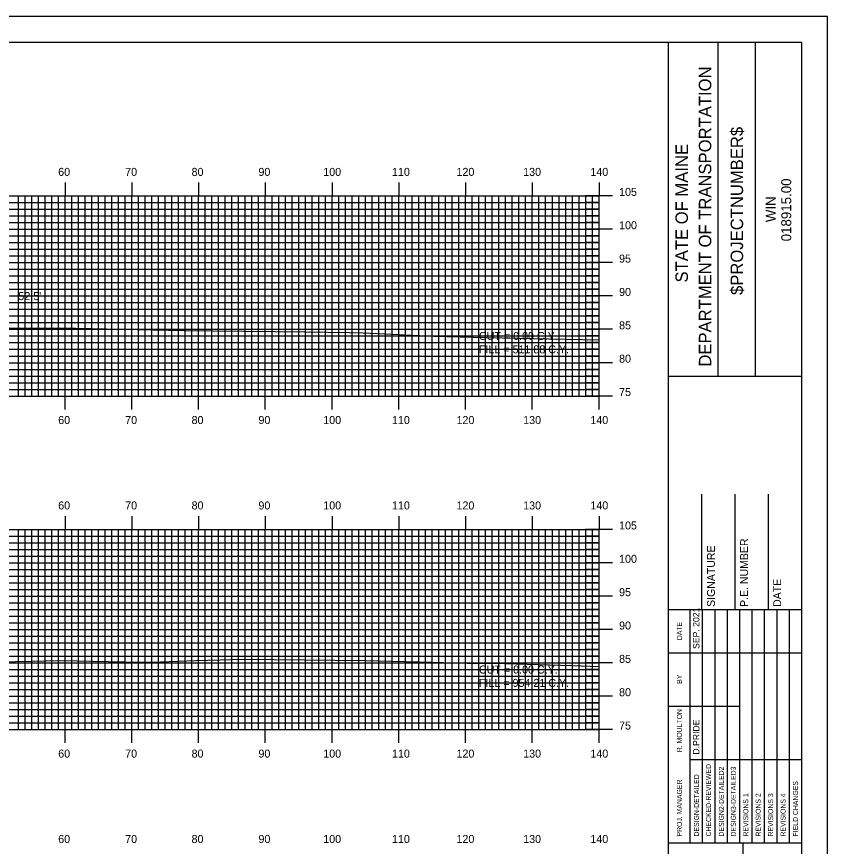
# Model space of a CAD drawing. Extents: x 2059 to 2403, y -1658 to -1438.
# Drawn here: x 2277.9 to 2399.4, y -1562.1 to -1437.7 of the extents above; entities that cross this region are included whole.
import ezdxf

# ---------------------------------------------------------------- set-up
doc = ezdxf.new("R2010")
doc.units = 0
for name, color, linetype in [('BORDER', 7, 'Continuous'), ('D_Text_Standard', 7, 'Continuous'), ('H_V ANNOTATION', 7, 'Continuous'), ('MAJOR', 7, 'Continuous'), ('MINOR', 7, 'Continuous'), ('PLOT BOUNDARY', 7, 'Continuous'), ('S_Roadway_Centerline', 7, 'Continuous')]:
    doc.layers.add(name, color=color, linetype=linetype)

msp = doc.modelspace()

# ---------------------------------------------------------------- linework, layer by layer
at = {"layer": 'BORDER'}
for p, q in [((2375.59, -1651.6), (2375.59, -1441.6)), ((2383.04, -1491.61), (2383.04, -1441.61)), ((2388.63, -1491.61), (2388.63, -1441.61)), ((2375.59, -1491.62), (2395.59, -1491.62)), ((2380.59, -1526.6), (2380.59, -1509.3)), ((2385.59, -1526.6), (2385.59, -1509.3)), ((2390.59, -1526.6), (2390.59, -1509.3)), ((2375.59, -1526.6), (2395.59, -1526.6)), ((2375.59, -1561.6), (2395.59, -1561.6)), ((2386.77, -1631.6), (2386.77, -1561.6))]:
    msp.add_line(p, q, dxfattribs=at)
msp.add_lwpolyline([(2075.59, -1651.6), (2395.59, -1651.6), (2395.59, -1441.6), (2075.59, -1441.6)], close=True, dxfattribs=at)
for points in [[(2378.82, -1533.1), (2378.82, -1526.6)], [(2380.68, -1561.59), (2380.68, -1526.6)], [(2382.54, -1526.6), (2382.54, -1561.59)], [(2384.41, -1561.59), (2384.41, -1526.6)], [(2386.27, -1561.59), (2386.27, -1526.6)], [(2388.14, -1561.59), (2388.14, -1526.6)], [(2390, -1561.59), (2390, -1526.6)], [(2391.86, -1561.59), (2391.86, -1526.6)], [(2393.73, -1561.59), (2393.73, -1526.6)], [(2378.82, -1561.59), (2378.82, -1528.01)], [(2375.59, -1533.1), (2395.59, -1533.1)], [(2375.59, -1541.1), (2378.82, -1541.1)], [(2378.82, -1541.1), (2386.27, -1541.1)], [(2378.82, -1549.1), (2395.59, -1549.1)]]:
    msp.add_lwpolyline(points, dxfattribs=at)
at = {"layer": 'MAJOR'}
for p, q in [((2285.19, -1462.6), (2285.19, -1464.6)), ((2295.19, -1462.6), (2295.19, -1464.6)), ((2305.19, -1462.6), (2305.19, -1464.6)), ((2315.19, -1462.6), (2315.19, -1464.6)), ((2325.19, -1462.6), (2325.19, -1464.6)), ((2335.19, -1462.6), (2335.19, -1464.6)), ((2345.19, -1462.6), (2345.19, -1464.6)), ((2355.19, -1462.6), (2355.19, -1464.6)), ((2365.19, -1462.6), (2365.19, -1464.6)), ((2085.19, -1464.6), (2365.19, -1464.6)), ((2085.19, -1464.6), (2365.19, -1464.6)), ((2285.19, -1494.6), (2285.19, -1464.6)), ((2295.19, -1494.6), (2295.19, -1464.6)), ((2305.19, -1494.6), (2305.19, -1464.6)), ((2315.19, -1494.6), (2315.19, -1464.6)), ((2325.19, -1494.6), (2325.19, -1464.6)), ((2335.19, -1494.6), (2335.19, -1464.6)), ((2345.19, -1494.6), (2345.19, -1464.6)), ((2355.19, -1494.6), (2355.19, -1464.6)), ((2367.19, -1464.6), (2363.18, -1464.6)), ((2365.19, -1494.6), (2365.19, -1464.6)), ((2365.19, -1494.6), (2365.19, -1464.6)), ((2085.19, -1469.6), (2365.19, -1469.6)), ((2367.19, -1469.6), (2363.18, -1469.6)), ((2085.19, -1474.6), (2365.19, -1474.6)), ((2367.19, -1474.6), (2363.18, -1474.6)), ((2085.19, -1479.6), (2365.19, -1479.6)), ((2367.19, -1479.6), (2363.18, -1479.6)), ((2085.19, -1484.6), (2365.19, -1484.6)), ((2367.19, -1484.6), (2363.18, -1484.6)), ((2085.19, -1489.6), (2365.19, -1489.6)), ((2367.19, -1489.6), (2363.18, -1489.6)), ((2085.19, -1494.6), (2365.19, -1494.6)), ((2085.19, -1494.6), (2365.19, -1494.6)), ((2285.19, -1496.61), (2285.19, -1494.6)), ((2295.19, -1496.61), (2295.19, -1494.6)), ((2305.19, -1496.61), (2305.19, -1494.6)), ((2315.19, -1496.61), (2315.19, -1494.6)), ((2325.19, -1496.61), (2325.19, -1494.6)), ((2335.19, -1496.61), (2335.19, -1494.6)), ((2345.19, -1496.61), (2345.19, -1494.6)), ((2355.19, -1496.61), (2355.19, -1494.6)), ((2367.19, -1494.6), (2363.18, -1494.6)), ((2365.19, -1496.61), (2365.19, -1494.6)), ((2285.19, -1512.6), (2285.19, -1514.6)), ((2295.19, -1512.6), (2295.19, -1514.6)), ((2305.19, -1512.6), (2305.19, -1514.6)), ((2315.19, -1512.6), (2315.19, -1514.6)), ((2325.19, -1512.6), (2325.19, -1514.6)), ((2335.19, -1512.6), (2335.19, -1514.6)), ((2345.19, -1512.6), (2345.19, -1514.6)), ((2355.19, -1512.6), (2355.19, -1514.6)), ((2365.19, -1512.6), (2365.19, -1514.6)), ((2085.19, -1514.6), (2365.19, -1514.6)), ((2085.19, -1514.6), (2365.19, -1514.6)), ((2285.19, -1544.6), (2285.19, -1514.6)), ((2295.19, -1544.6), (2295.19, -1514.6)), ((2305.19, -1544.6), (2305.19, -1514.6)), ((2315.19, -1544.6), (2315.19, -1514.6)), ((2325.19, -1544.6), (2325.19, -1514.6)), ((2335.19, -1544.6), (2335.19, -1514.6)), ((2345.19, -1544.6), (2345.19, -1514.6)), ((2355.19, -1544.6), (2355.19, -1514.6)), ((2367.19, -1514.6), (2363.18, -1514.6)), ((2365.19, -1544.6), (2365.19, -1514.6)), ((2365.19, -1544.6), (2365.19, -1514.6)), ((2085.19, -1519.6), (2365.19, -1519.6)), ((2367.19, -1519.6), (2363.18, -1519.6)), ((2085.19, -1524.6), (2365.19, -1524.6)), ((2367.19, -1524.6), (2363.18, -1524.6)), ((2085.19, -1529.6), (2365.19, -1529.6)), ((2367.19, -1529.6), (2363.18, -1529.6)), ((2085.19, -1534.6), (2365.19, -1534.6)), ((2367.19, -1534.6), (2363.18, -1534.6)), ((2085.19, -1539.6), (2365.19, -1539.6)), ((2367.19, -1539.6), (2363.18, -1539.6)), ((2085.19, -1544.6), (2365.19, -1544.6)), ((2085.19, -1544.6), (2365.19, -1544.6)), ((2285.19, -1546.61), (2285.19, -1544.6)), ((2295.19, -1546.61), (2295.19, -1544.6)), ((2305.19, -1546.61), (2305.19, -1544.6)), ((2315.19, -1546.61), (2315.19, -1544.6)), ((2325.19, -1546.61), (2325.19, -1544.6)), ((2335.19, -1546.61), (2335.19, -1544.6)), ((2345.19, -1546.61), (2345.19, -1544.6)), ((2355.19, -1546.61), (2355.19, -1544.6)), ((2367.19, -1544.6), (2363.18, -1544.6)), ((2365.19, -1546.61), (2365.19, -1544.6))]:
    msp.add_line(p, q, dxfattribs=at)
at = {"layer": 'MINOR'}
for p, q in [((2278.19, -1494.6), (2278.19, -1464.6)), ((2279.19, -1494.6), (2279.19, -1464.6)), ((2280.19, -1494.6), (2280.19, -1464.6)), ((2281.19, -1494.6), (2281.19, -1464.6)), ((2282.19, -1494.6), (2282.19, -1464.6)), ((2283.19, -1494.6), (2283.19, -1464.6)), ((2284.19, -1494.6), (2284.19, -1464.6)), ((2286.19, -1494.6), (2286.19, -1464.6)), ((2287.19, -1494.6), (2287.19, -1464.6)), ((2288.19, -1494.6), (2288.19, -1464.6)), ((2289.19, -1494.6), (2289.19, -1464.6)), ((2290.19, -1494.6), (2290.19, -1464.6)), ((2291.19, -1494.6), (2291.19, -1464.6)), ((2292.19, -1494.6), (2292.19, -1464.6)), ((2293.19, -1494.6), (2293.19, -1464.6)), ((2294.19, -1494.6), (2294.19, -1464.6)), ((2296.19, -1494.6), (2296.19, -1464.6)), ((2297.19, -1494.6), (2297.19, -1464.6)), ((2298.19, -1494.6), (2298.19, -1464.6)), ((2299.19, -1494.6), (2299.19, -1464.6)), ((2300.19, -1494.6), (2300.19, -1464.6)), ((2301.19, -1494.6), (2301.19, -1464.6)), ((2302.19, -1494.6), (2302.19, -1464.6)), ((2303.19, -1494.6), (2303.19, -1464.6)), ((2304.19, -1494.6), (2304.19, -1464.6)), ((2306.19, -1494.6), (2306.19, -1464.6)), ((2307.19, -1494.6), (2307.19, -1464.6)), ((2308.19, -1494.6), (2308.19, -1464.6)), ((2309.19, -1494.6), (2309.19, -1464.6)), ((2310.19, -1494.6), (2310.19, -1464.6)), ((2311.19, -1494.6), (2311.19, -1464.6)), ((2312.19, -1494.6), (2312.19, -1464.6)), ((2313.19, -1494.6), (2313.19, -1464.6)), ((2314.19, -1494.6), (2314.19, -1464.6)), ((2316.19, -1494.6), (2316.19, -1464.6)), ((2317.19, -1494.6), (2317.19, -1464.6)), ((2318.19, -1494.6), (2318.19, -1464.6)), ((2319.19, -1494.6), (2319.19, -1464.6)), ((2320.19, -1494.6), (2320.19, -1464.6)), ((2321.19, -1494.6), (2321.19, -1464.6)), ((2322.19, -1494.6), (2322.19, -1464.6)), ((2323.19, -1494.6), (2323.19, -1464.6)), ((2324.19, -1494.6), (2324.19, -1464.6)), ((2326.19, -1494.6), (2326.19, -1464.6)), ((2327.19, -1494.6), (2327.19, -1464.6)), ((2328.19, -1494.6), (2328.19, -1464.6)), ((2329.19, -1494.6), (2329.19, -1464.6)), ((2330.19, -1494.6), (2330.19, -1464.6)), ((2331.19, -1494.6), (2331.19, -1464.6)), ((2332.19, -1494.6), (2332.19, -1464.6)), ((2333.19, -1494.6), (2333.19, -1464.6)), ((2334.19, -1494.6), (2334.19, -1464.6)), ((2336.19, -1494.6), (2336.19, -1464.6)), ((2337.19, -1494.6), (2337.19, -1464.6)), ((2338.19, -1494.6), (2338.19, -1464.6)), ((2339.19, -1494.6), (2339.19, -1464.6)), ((2340.19, -1494.6), (2340.19, -1464.6)), ((2341.19, -1494.6), (2341.19, -1464.6)), ((2342.19, -1494.6), (2342.19, -1464.6)), ((2343.19, -1494.6), (2343.19, -1464.6)), ((2344.19, -1494.6), (2344.19, -1464.6)), ((2346.19, -1494.6), (2346.19, -1464.6)), ((2347.19, -1494.6), (2347.19, -1464.6)), ((2348.19, -1494.6), (2348.19, -1464.6)), ((2349.19, -1494.6), (2349.19, -1464.6)), ((2350.19, -1494.6), (2350.19, -1464.6)), ((2351.19, -1494.6), (2351.19, -1464.6)), ((2352.19, -1494.6), (2352.19, -1464.6)), ((2353.19, -1494.6), (2353.19, -1464.6)), ((2354.19, -1494.6), (2354.19, -1464.6)), ((2356.19, -1494.6), (2356.19, -1464.6)), ((2357.19, -1494.6), (2357.19, -1464.6)), ((2358.19, -1494.6), (2358.19, -1464.6)), ((2359.19, -1494.6), (2359.19, -1464.6)), ((2360.19, -1494.6), (2360.19, -1464.6)), ((2361.19, -1494.6), (2361.19, -1464.6)), ((2362.19, -1494.6), (2362.19, -1464.6)), ((2363.19, -1494.6), (2363.19, -1464.6)), ((2364.19, -1494.6), (2364.19, -1464.6)), ((2085.19, -1465.6), (2365.19, -1465.6)), ((2365.19, -1465.6), (2363.18, -1465.6)), ((2085.19, -1466.6), (2365.19, -1466.6)), ((2085.19, -1467.6), (2365.19, -1467.6)), ((2365.19, -1466.6), (2363.18, -1466.6)), ((2365.19, -1467.6), (2363.18, -1467.6)), ((2085.19, -1468.6), (2365.19, -1468.6)), ((2365.19, -1468.6), (2363.18, -1468.6)), ((2085.19, -1470.6), (2365.19, -1470.6)), ((2365.19, -1470.6), (2363.18, -1470.6)), ((2085.19, -1471.6), (2365.19, -1471.6)), ((2085.19, -1472.6), (2365.19, -1472.6)), ((2365.19, -1471.6), (2363.18, -1471.6)), ((2365.19, -1472.6), (2363.18, -1472.6)), ((2085.19, -1473.6), (2365.19, -1473.6)), ((2365.19, -1473.6), (2363.18, -1473.6)), ((2085.19, -1475.6), (2365.19, -1475.6)), ((2365.19, -1475.6), (2363.18, -1475.6)), ((2085.19, -1476.6), (2365.19, -1476.6)), ((2085.19, -1477.6), (2365.19, -1477.6)), ((2365.19, -1476.6), (2363.18, -1476.6)), ((2365.19, -1477.6), (2363.18, -1477.6)), ((2085.19, -1478.6), (2365.19, -1478.6)), ((2365.19, -1478.6), (2363.18, -1478.6)), ((2085.19, -1480.6), (2365.19, -1480.6)), ((2365.19, -1480.6), (2363.18, -1480.6)), ((2085.19, -1481.6), (2365.19, -1481.6)), ((2085.19, -1482.6), (2365.19, -1482.6)), ((2365.19, -1481.6), (2363.18, -1481.6)), ((2365.19, -1482.6), (2363.18, -1482.6)), ((2085.19, -1483.6), (2365.19, -1483.6)), ((2365.19, -1483.6), (2363.18, -1483.6)), ((2085.19, -1485.6), (2365.19, -1485.6)), ((2365.19, -1485.6), (2363.18, -1485.6)), ((2085.19, -1486.6), (2365.19, -1486.6)), ((2085.19, -1487.6), (2365.19, -1487.6)), ((2365.19, -1486.6), (2363.18, -1486.6)), ((2365.19, -1487.6), (2363.18, -1487.6)), ((2085.19, -1488.6), (2365.19, -1488.6)), ((2365.19, -1488.6), (2363.18, -1488.6)), ((2085.19, -1490.6), (2365.19, -1490.6)), ((2365.19, -1490.6), (2363.18, -1490.6)), ((2085.19, -1491.6), (2365.19, -1491.6)), ((2085.19, -1492.6), (2365.19, -1492.6)), ((2365.19, -1491.6), (2363.18, -1491.6)), ((2365.19, -1492.6), (2363.18, -1492.6)), ((2085.19, -1493.6), (2365.19, -1493.6)), ((2365.19, -1493.6), (2363.18, -1493.6)), ((2278.19, -1544.6), (2278.19, -1514.6)), ((2279.19, -1544.6), (2279.19, -1514.6)), ((2280.19, -1544.6), (2280.19, -1514.6)), ((2281.19, -1544.6), (2281.19, -1514.6)), ((2282.19, -1544.6), (2282.19, -1514.6)), ((2283.19, -1544.6), (2283.19, -1514.6)), ((2284.19, -1544.6), (2284.19, -1514.6)), ((2286.19, -1544.6), (2286.19, -1514.6)), ((2287.19, -1544.6), (2287.19, -1514.6)), ((2288.19, -1544.6), (2288.19, -1514.6)), ((2289.19, -1544.6), (2289.19, -1514.6)), ((2290.19, -1544.6), (2290.19, -1514.6)), ((2291.19, -1544.6), (2291.19, -1514.6)), ((2292.19, -1544.6), (2292.19, -1514.6)), ((2293.19, -1544.6), (2293.19, -1514.6)), ((2294.19, -1544.6), (2294.19, -1514.6)), ((2296.19, -1544.6), (2296.19, -1514.6)), ((2297.19, -1544.6), (2297.19, -1514.6)), ((2298.19, -1544.6), (2298.19, -1514.6)), ((2299.19, -1544.6), (2299.19, -1514.6)), ((2300.19, -1544.6), (2300.19, -1514.6)), ((2301.19, -1544.6), (2301.19, -1514.6)), ((2302.19, -1544.6), (2302.19, -1514.6)), ((2303.19, -1544.6), (2303.19, -1514.6)), ((2304.19, -1544.6), (2304.19, -1514.6)), ((2306.19, -1544.6), (2306.19, -1514.6)), ((2307.19, -1544.6), (2307.19, -1514.6)), ((2308.19, -1544.6), (2308.19, -1514.6)), ((2309.19, -1544.6), (2309.19, -1514.6)), ((2310.19, -1544.6), (2310.19, -1514.6)), ((2311.19, -1544.6), (2311.19, -1514.6)), ((2312.19, -1544.6), (2312.19, -1514.6)), ((2313.19, -1544.6), (2313.19, -1514.6)), ((2314.19, -1544.6), (2314.19, -1514.6)), ((2316.19, -1544.6), (2316.19, -1514.6)), ((2317.19, -1544.6), (2317.19, -1514.6)), ((2318.19, -1544.6), (2318.19, -1514.6)), ((2319.19, -1544.6), (2319.19, -1514.6)), ((2320.19, -1544.6), (2320.19, -1514.6)), ((2321.19, -1544.6), (2321.19, -1514.6)), ((2322.19, -1544.6), (2322.19, -1514.6)), ((2323.19, -1544.6), (2323.19, -1514.6)), ((2324.19, -1544.6), (2324.19, -1514.6)), ((2326.19, -1544.6), (2326.19, -1514.6)), ((2327.19, -1544.6), (2327.19, -1514.6)), ((2328.19, -1544.6), (2328.19, -1514.6)), ((2329.19, -1544.6), (2329.19, -1514.6)), ((2330.19, -1544.6), (2330.19, -1514.6)), ((2331.19, -1544.6), (2331.19, -1514.6)), ((2332.19, -1544.6), (2332.19, -1514.6)), ((2333.19, -1544.6), (2333.19, -1514.6)), ((2334.19, -1544.6), (2334.19, -1514.6)), ((2336.19, -1544.6), (2336.19, -1514.6)), ((2337.19, -1544.6), (2337.19, -1514.6)), ((2338.19, -1544.6), (2338.19, -1514.6)), ((2339.19, -1544.6), (2339.19, -1514.6)), ((2340.19, -1544.6), (2340.19, -1514.6)), ((2341.19, -1544.6), (2341.19, -1514.6)), ((2342.19, -1544.6), (2342.19, -1514.6)), ((2343.19, -1544.6), (2343.19, -1514.6)), ((2344.19, -1544.6), (2344.19, -1514.6)), ((2346.19, -1544.6), (2346.19, -1514.6)), ((2347.19, -1544.6), (2347.19, -1514.6)), ((2348.19, -1544.6), (2348.19, -1514.6)), ((2349.19, -1544.6), (2349.19, -1514.6)), ((2350.19, -1544.6), (2350.19, -1514.6)), ((2351.19, -1544.6), (2351.19, -1514.6)), ((2352.19, -1544.6), (2352.19, -1514.6)), ((2353.19, -1544.6), (2353.19, -1514.6)), ((2354.19, -1544.6), (2354.19, -1514.6)), ((2356.19, -1544.6), (2356.19, -1514.6)), ((2357.19, -1544.6), (2357.19, -1514.6)), ((2358.19, -1544.6), (2358.19, -1514.6)), ((2359.19, -1544.6), (2359.19, -1514.6)), ((2360.19, -1544.6), (2360.19, -1514.6)), ((2361.19, -1544.6), (2361.19, -1514.6)), ((2362.19, -1544.6), (2362.19, -1514.6)), ((2363.19, -1544.6), (2363.19, -1514.6)), ((2364.19, -1544.6), (2364.19, -1514.6)), ((2085.19, -1515.6), (2365.19, -1515.6)), ((2365.19, -1515.6), (2363.18, -1515.6)), ((2085.19, -1516.6), (2365.19, -1516.6)), ((2365.19, -1516.6), (2363.18, -1516.6)), ((2085.19, -1517.6), (2365.19, -1517.6)), ((2085.19, -1518.6), (2365.19, -1518.6)), ((2365.19, -1517.6), (2363.18, -1517.6)), ((2365.19, -1518.6), (2363.18, -1518.6)), ((2085.19, -1520.6), (2365.19, -1520.6)), ((2365.19, -1520.6), (2363.18, -1520.6)), ((2085.19, -1521.6), (2365.19, -1521.6)), ((2365.19, -1521.6), (2363.18, -1521.6)), ((2085.19, -1522.6), (2365.19, -1522.6)), ((2085.19, -1523.6), (2365.19, -1523.6)), ((2365.19, -1522.6), (2363.18, -1522.6)), ((2365.19, -1523.6), (2363.18, -1523.6)), ((2085.19, -1525.6), (2365.19, -1525.6)), ((2365.19, -1525.6), (2363.18, -1525.6)), ((2085.19, -1526.6), (2365.19, -1526.6)), ((2365.19, -1526.6), (2363.18, -1526.6)), ((2085.19, -1527.6), (2365.19, -1527.6)), ((2085.19, -1528.6), (2365.19, -1528.6)), ((2365.19, -1527.6), (2363.18, -1527.6)), ((2365.19, -1528.6), (2363.18, -1528.6)), ((2085.19, -1530.6), (2365.19, -1530.6)), ((2365.19, -1530.6), (2363.18, -1530.6)), ((2085.19, -1531.6), (2365.19, -1531.6)), ((2365.19, -1531.6), (2363.18, -1531.6)), ((2085.19, -1532.6), (2365.19, -1532.6)), ((2085.19, -1533.6), (2365.19, -1533.6)), ((2365.19, -1532.6), (2363.18, -1532.6)), ((2365.19, -1533.6), (2363.18, -1533.6)), ((2085.19, -1535.6), (2365.19, -1535.6)), ((2365.19, -1535.6), (2363.18, -1535.6)), ((2085.19, -1536.6), (2365.19, -1536.6)), ((2365.19, -1536.6), (2363.18, -1536.6)), ((2085.19, -1537.6), (2365.19, -1537.6)), ((2085.19, -1538.6), (2365.19, -1538.6)), ((2365.19, -1537.6), (2363.18, -1537.6)), ((2365.19, -1538.6), (2363.18, -1538.6)), ((2085.19, -1540.6), (2365.19, -1540.6)), ((2365.19, -1540.6), (2363.18, -1540.6)), ((2085.19, -1541.6), (2365.19, -1541.6)), ((2365.19, -1541.6), (2363.18, -1541.6)), ((2085.19, -1542.6), (2365.19, -1542.6)), ((2085.19, -1543.6), (2365.19, -1543.6)), ((2365.19, -1542.6), (2363.18, -1542.6)), ((2365.19, -1543.6), (2363.18, -1543.6))]:
    msp.add_line(p, q, dxfattribs=at)
at = {"layer": 'PLOT BOUNDARY'}
msp.add_lwpolyline([(2059.4, -1657.72), (2399.4, -1657.72), (2399.4, -1437.72), (2059.4, -1437.72)], close=True, dxfattribs=at)
at = {"layer": 'S_Roadway_Centerline'}
for points in [[(2275.15, -1484.38), (2286.77, -1484.42), (2303.01, -1484.8), (2307.3, -1484.84), (2321.28, -1485), (2327.81, -1485.07), (2329.83, -1485.14), (2340.42, -1485.62), (2348.33, -1485.84), (2357.74, -1486.05), (2365.19, -1486.19)], [(2275.41, -1534.43), (2284.59, -1534.24), (2294.02, -1534.43), (2298.15, -1534.49), (2304.8, -1534.25), (2312.02, -1534.04), (2321.01, -1534.14), (2330.23, -1534.25), (2338.28, -1534.43), (2345.43, -1534.62), (2349.34, -1534.62), (2361.18, -1534.99), (2365.19, -1535.13)]]:
    msp.add_lwpolyline(points, dxfattribs=at)

# ---------------------------------------------------------------- texts
at = {"layer": 'BORDER'}
for s, height, p in [('DEPARTMENT OF TRANSPORTATION', 1.8635, (2382, -1490.19)), ('$PROJECTNUMBER$', 1.8635, (2386.77, -1479.45)), ('STATE OF MAINE', 1.8635, (2378.5, -1477.58)), ('018915.00', 1.491, (2393.98, -1471.41)), ('WIN', 1.491, (2391.66, -1468.54)), ('P.E. NUMBER', 1.1811, (2387.51, -1526.21)), ('SIGNATURE', 1.181, (2382.55, -1526.21)), ('DATE', 1.181, (2392.47, -1526.21)), ('SEP. 2021', 0.969, (2380.23, -1532.51)), ('DATE', 0.743, (2377.6, -1531.19)), ('BY', 0.743, (2377.6, -1537.73)), ('R. MOULTON', 0.745, (2377.6, -1547.99)), ('D.PRIDE', 0.969, (2380.23, -1548.35)), ('CHECKED-REVIEWED', 0.7455, (2381.95, -1560.62)), ('DESIGN2-DETAILED2', 0.7455, (2383.89, -1560.62)), ('DESIGN3-DETAILED3', 0.7455, (2385.68, -1560.62)), ('DESIGN-DETAILED', 0.7455, (2380.16, -1560.62)), ('PROJ. MANAGER', 0.7455, (2377.6, -1560.62)), ('FIELD CHANGES', 0.7455, (2394.99, -1560.62)), ('REVISIONS 1', 0.7455, (2387.54, -1560.62)), ('REVISIONS 2', 0.7455, (2389.4, -1560.62)), ('REVISIONS 3', 0.7455, (2391.27, -1560.62)), ('REVISIONS 4', 0.7455, (2393.13, -1560.62))]:
    msp.add_text(s, height=height, rotation=90, dxfattribs=at).set_placement(p)
at = {"layer": 'D_Text_Standard'}
for s, p in [("52.5'", (2278.19, -1480.22)), ('CUT = 0.00 C.Y.', (2347.19, -1486.2)), ('FILL = 511.88 C.Y.', (2347.19, -1488.2)), ('CUT = 0.00 C.Y.', (2347.19, -1536.2)), ('FILL = 954.21 C.Y.', (2347.19, -1538.2))]:
    msp.add_text(s, height=1.2, dxfattribs=at).set_placement(p)
at = {"layer": 'H_V ANNOTATION'}
for s, p in [('60', (2284.16, -1461.6)), ('70', (2294.19, -1461.6)), ('80', (2304.14, -1461.6)), ('90', (2314.16, -1461.6)), ('100', (2323.87, -1461.6)), ('110', (2334.17, -1461.6)), ('120', (2343.83, -1461.6)), ('130', (2353.82, -1461.6)), ('140', (2363.89, -1461.6)), ('105', (2368.19, -1464.6)), ('100', (2368.19, -1469.6)), ('95', (2368.19, -1474.6)), ('90', (2368.19, -1479.6)), ('85', (2368.19, -1484.6)), ('80', (2368.19, -1489.6)), ('75', (2368.19, -1494.6)), ('60', (2284.16, -1498.8)), ('70', (2294.19, -1498.8)), ('80', (2304.14, -1498.8)), ('90', (2314.16, -1498.8)), ('100', (2323.87, -1498.8)), ('110', (2334.17, -1498.8)), ('120', (2343.83, -1498.8)), ('130', (2353.82, -1498.8)), ('140', (2363.89, -1498.8)), ('60', (2284.16, -1511.6)), ('70', (2294.19, -1511.6)), ('80', (2304.14, -1511.6)), ('90', (2314.16, -1511.6)), ('100', (2323.87, -1511.6)), ('110', (2334.17, -1511.6)), ('120', (2343.83, -1511.6)), ('130', (2353.82, -1511.6)), ('140', (2363.89, -1511.6)), ('105', (2368.19, -1514.6)), ('100', (2368.19, -1519.6)), ('95', (2368.19, -1524.6)), ('90', (2368.19, -1529.6)), ('85', (2368.19, -1534.6)), ('80', (2368.19, -1539.6)), ('75', (2368.19, -1544.6)), ('60', (2284.16, -1548.8)), ('70', (2294.19, -1548.8)), ('80', (2304.14, -1548.8)), ('90', (2314.16, -1548.8)), ('100', (2323.87, -1548.8)), ('110', (2334.17, -1548.8)), ('120', (2343.83, -1548.8)), ('130', (2353.82, -1548.8)), ('140', (2363.89, -1548.8)), ('60', (2284.16, -1561.6)), ('70', (2294.19, -1561.6)), ('80', (2304.14, -1561.6)), ('90', (2314.16, -1561.6)), ('100', (2323.87, -1561.6)), ('110', (2334.17, -1561.6)), ('120', (2343.83, -1561.6)), ('130', (2353.82, -1561.6)), ('140', (2363.89, -1561.6))]:
    msp.add_text(s, height=1.2, dxfattribs=at).set_placement(p)

doc.saveas('drawing.dxf')
